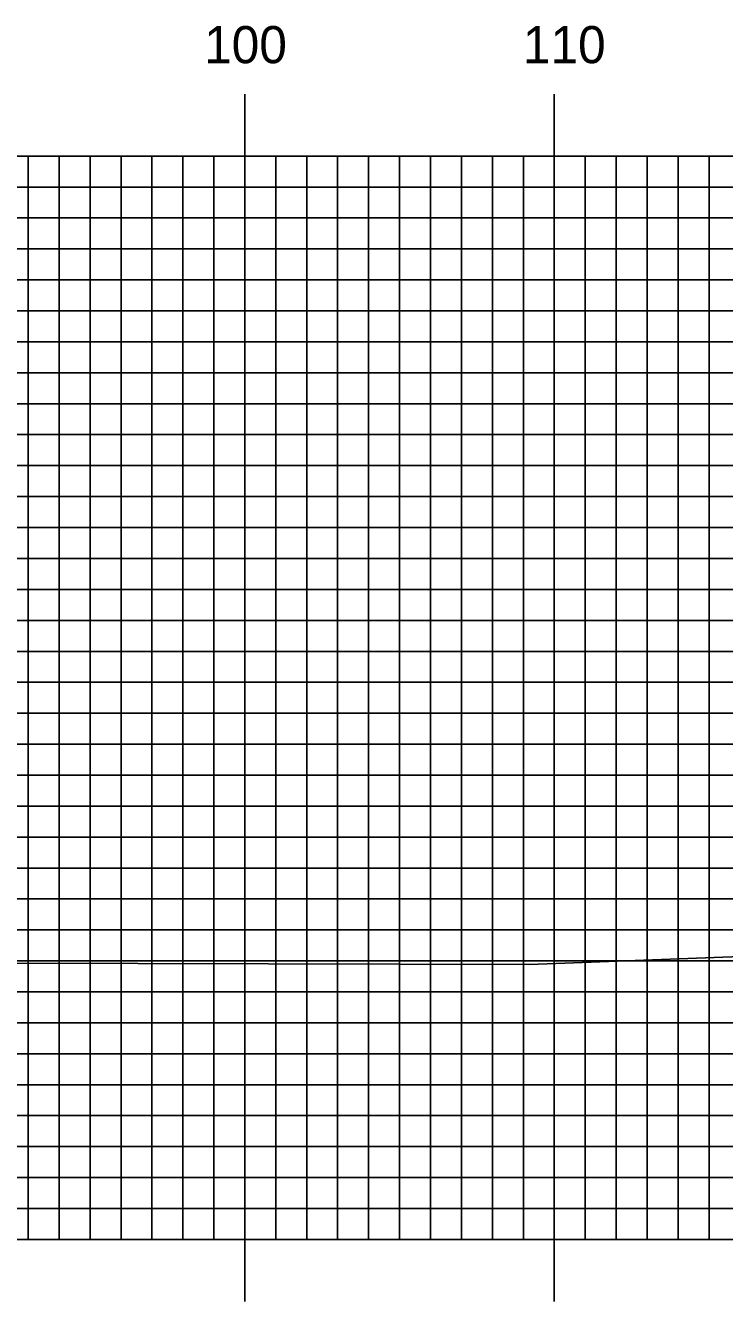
# Model space of a CAD drawing. Extents: x 1789337 to 1789680, y 442591 to 442811.
# Drawn here: x 1789595.58 to 1789618.17, y 442666.66 to 442707.88 of the extents above; entities that cross this region are included whole.
import ezdxf

# ---------------------------------------------------------------- set-up
doc = ezdxf.new("R2010")
doc.units = 0
for name, color, linetype in [('H_V ANNOTATION', 7, 'Continuous'), ('MAJOR', 7, 'Continuous'), ('MINOR', 7, 'Continuous'), ('S_Roadway_Centerline', 7, 'Continuous')]:
    doc.layers.add(name, color=color, linetype=linetype)

msp = doc.modelspace()

# ---------------------------------------------------------------- linework, layer by layer
at = {"layer": 'MAJOR'}
for p, q in [((1789602.67, 442705.669), (1789602.67, 442703.665)), ((1789612.67, 442705.669), (1789612.67, 442703.665)), ((1789362.67, 442703.665), (1789642.67, 442703.665)), ((1789362.67, 442703.665), (1789642.67, 442703.665)), ((1789602.67, 442668.665), (1789602.67, 442703.665)), ((1789612.67, 442668.665), (1789612.67, 442703.665)), ((1789362.67, 442698.665), (1789642.67, 442698.665)), ((1789362.67, 442693.665), (1789642.67, 442693.665)), ((1789362.67, 442688.665), (1789642.67, 442688.665)), ((1789362.67, 442683.665), (1789642.67, 442683.665)), ((1789362.67, 442678.665), (1789642.67, 442678.665)), ((1789362.67, 442673.665), (1789642.67, 442673.665)), ((1789362.67, 442668.665), (1789642.67, 442668.665)), ((1789362.67, 442668.665), (1789642.67, 442668.665)), ((1789602.67, 442666.661), (1789602.67, 442668.665)), ((1789612.67, 442666.661), (1789612.67, 442668.665))]:
    msp.add_line(p, q, dxfattribs=at)
at = {"layer": 'MINOR'}
for p, q in [((1789595.67, 442668.665), (1789595.67, 442703.665)), ((1789596.67, 442668.665), (1789596.67, 442703.665)), ((1789597.67, 442668.665), (1789597.67, 442703.665)), ((1789598.67, 442668.665), (1789598.67, 442703.665)), ((1789599.67, 442668.665), (1789599.67, 442703.665)), ((1789600.67, 442668.665), (1789600.67, 442703.665)), ((1789601.67, 442668.665), (1789601.67, 442703.665)), ((1789603.67, 442668.665), (1789603.67, 442703.665)), ((1789604.67, 442668.665), (1789604.67, 442703.665)), ((1789605.67, 442668.665), (1789605.67, 442703.665)), ((1789606.67, 442668.665), (1789606.67, 442703.665)), ((1789607.67, 442668.665), (1789607.67, 442703.665)), ((1789608.67, 442668.665), (1789608.67, 442703.665)), ((1789609.67, 442668.665), (1789609.67, 442703.665)), ((1789610.67, 442668.665), (1789610.67, 442703.665)), ((1789611.67, 442668.665), (1789611.67, 442703.665)), ((1789613.67, 442668.665), (1789613.67, 442703.665)), ((1789614.67, 442668.665), (1789614.67, 442703.665)), ((1789615.67, 442668.665), (1789615.67, 442703.665)), ((1789616.67, 442668.665), (1789616.67, 442703.665)), ((1789617.67, 442668.665), (1789617.67, 442703.665)), ((1789362.67, 442702.665), (1789642.67, 442702.665)), ((1789362.67, 442701.665), (1789642.67, 442701.665)), ((1789362.67, 442700.665), (1789642.67, 442700.665)), ((1789362.67, 442699.665), (1789642.67, 442699.665)), ((1789362.67, 442697.665), (1789642.67, 442697.665)), ((1789362.67, 442696.665), (1789642.67, 442696.665)), ((1789362.67, 442695.665), (1789642.67, 442695.665)), ((1789362.67, 442694.665), (1789642.67, 442694.665)), ((1789362.67, 442692.665), (1789642.67, 442692.665)), ((1789362.67, 442691.665), (1789642.67, 442691.665)), ((1789362.67, 442690.665), (1789642.67, 442690.665)), ((1789362.67, 442689.665), (1789642.67, 442689.665)), ((1789362.67, 442687.665), (1789642.67, 442687.665)), ((1789362.67, 442686.665), (1789642.67, 442686.665)), ((1789362.67, 442685.665), (1789642.67, 442685.665)), ((1789362.67, 442684.665), (1789642.67, 442684.665)), ((1789362.67, 442682.665), (1789642.67, 442682.665)), ((1789362.67, 442681.665), (1789642.67, 442681.665)), ((1789362.67, 442680.665), (1789642.67, 442680.665)), ((1789362.67, 442679.665), (1789642.67, 442679.665)), ((1789362.67, 442677.665), (1789642.67, 442677.665)), ((1789362.67, 442676.665), (1789642.67, 442676.665)), ((1789362.67, 442675.665), (1789642.67, 442675.665)), ((1789362.67, 442674.665), (1789642.67, 442674.665)), ((1789362.67, 442672.665), (1789642.67, 442672.665)), ((1789362.67, 442671.665), (1789642.67, 442671.665)), ((1789362.67, 442670.665), (1789642.67, 442670.665)), ((1789362.67, 442669.665), (1789642.67, 442669.665))]:
    msp.add_line(p, q, dxfattribs=at)
at = {"layer": 'S_Roadway_Centerline'}
msp.add_lwpolyline([(1789556.809, 442676.443), (1789575.02, 442676.753), (1789580.206, 442676.802), (1789590.842, 442677.48), (1789592.389, 442677.598), (1789593.11, 442677.575), (1789595.002, 442677.586), (1789611.872, 442677.544), (1789628.922, 442678.192), (1789629.792, 442678.252), (1789630.682, 442678.254), (1789642.67, 442678.712)], dxfattribs=at)

# ---------------------------------------------------------------- texts
at = {"layer": 'H_V ANNOTATION'}
for s, p in [('100', (1789601.353, 442706.665)), ('110', (1789611.653, 442706.665))]:
    msp.add_text(s, height=1.2, dxfattribs=at).set_placement(p)

doc.saveas('drawing.dxf')
